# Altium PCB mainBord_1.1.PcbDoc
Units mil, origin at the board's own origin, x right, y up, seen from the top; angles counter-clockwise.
Board outline 3937.01 x 3149.61 mil, 2 copper layers (Top Layer, Bottom Layer); 51 components, 85 nets, 361 pads, 344 vias.
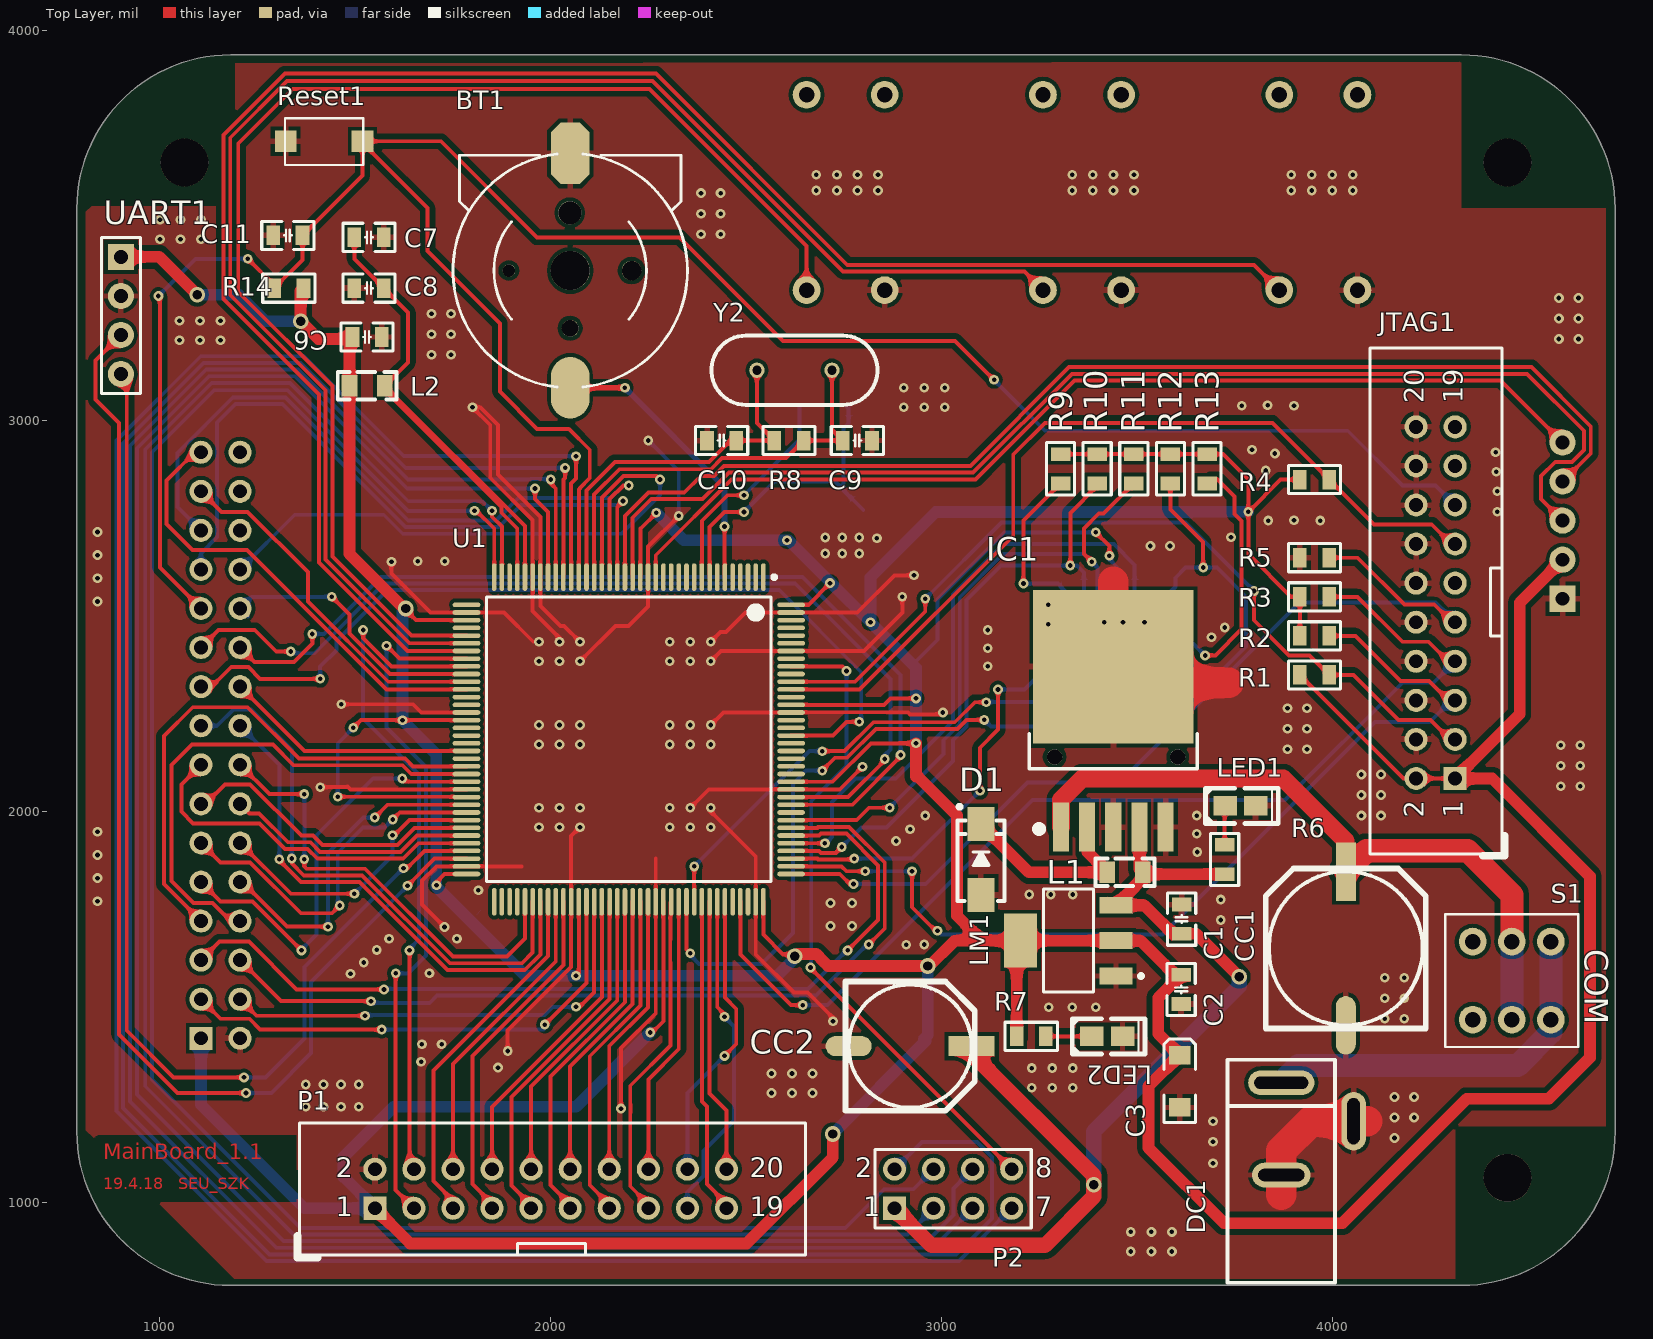
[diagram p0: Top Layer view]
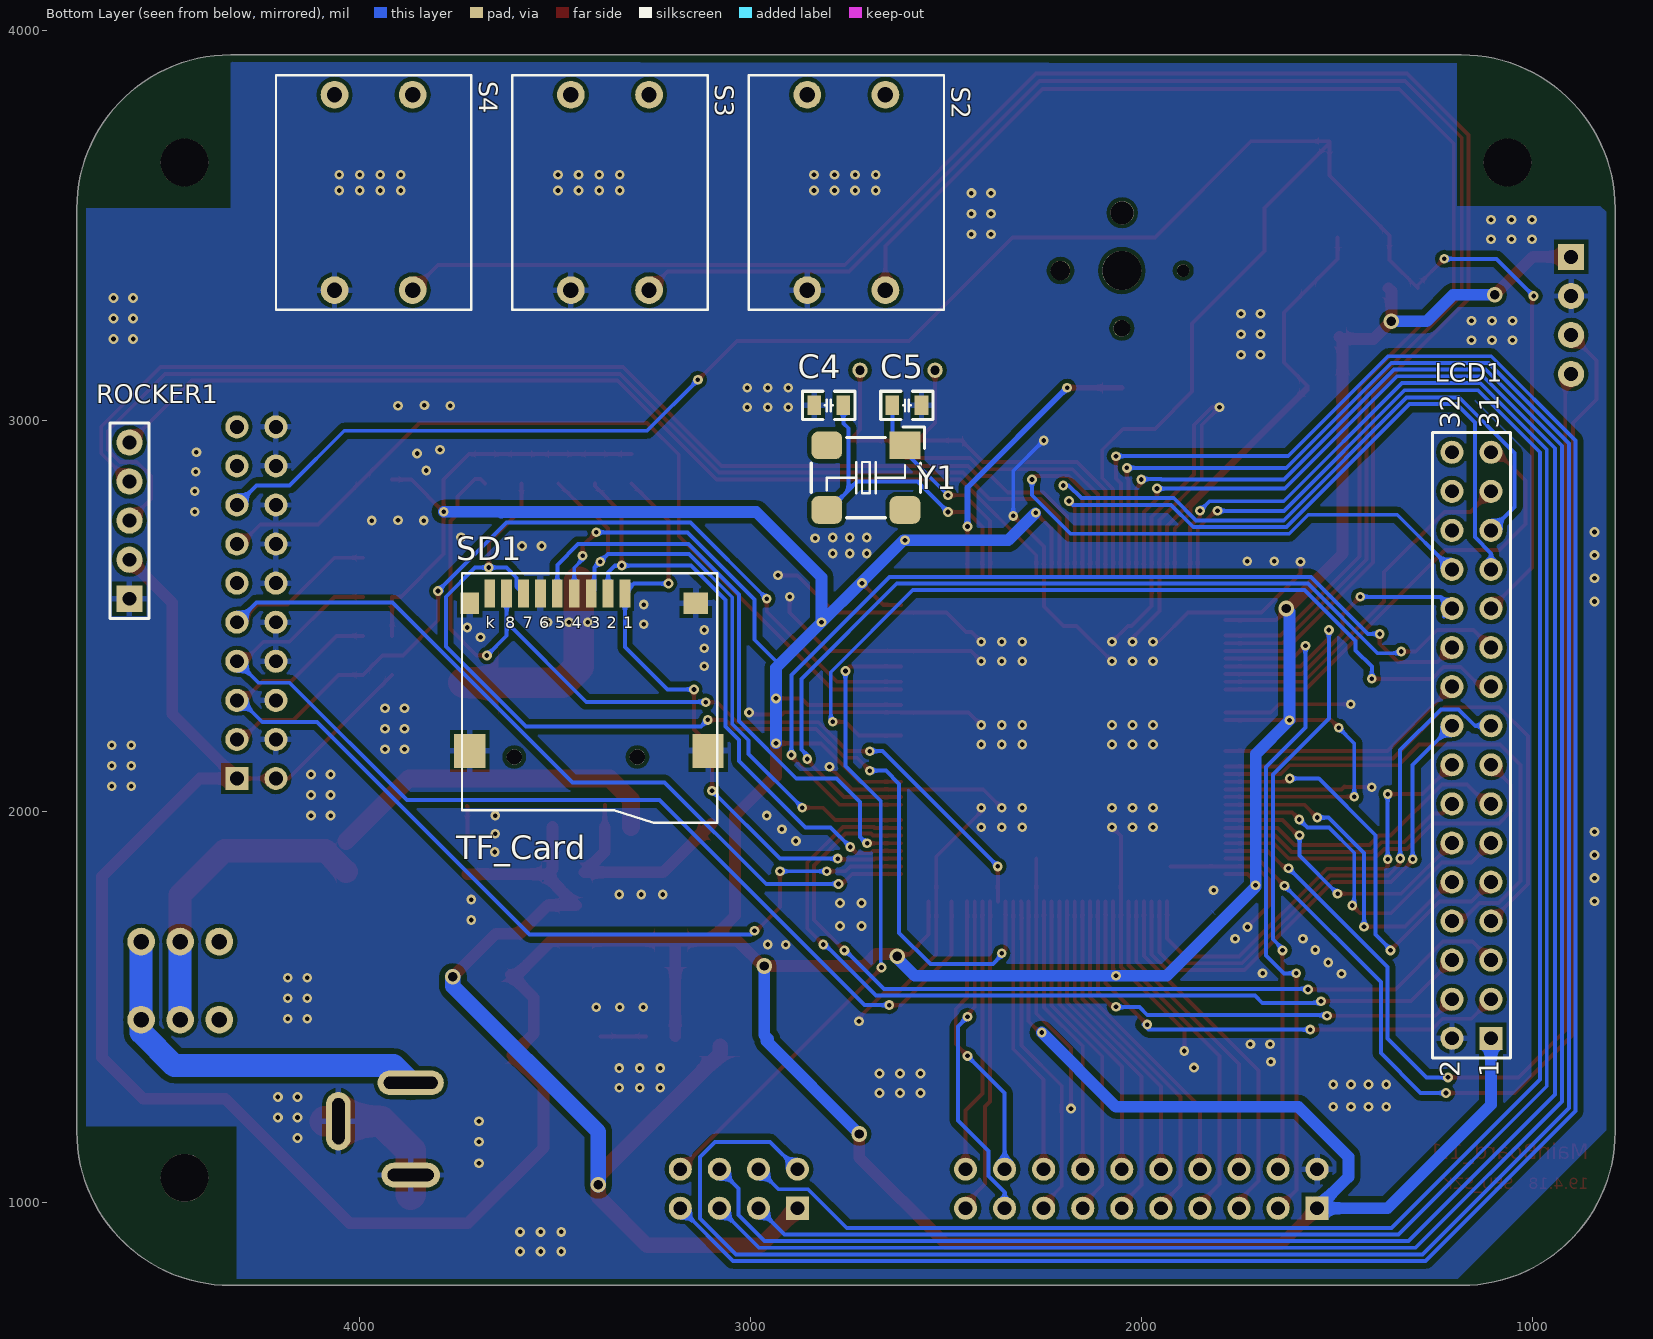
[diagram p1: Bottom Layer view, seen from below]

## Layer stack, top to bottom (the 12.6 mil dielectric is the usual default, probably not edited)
Top Solder: solder mask 0.4, Solder Resist, Dk 3.5
Top Layer: signal copper 1.4
Dielectric 1: dielectric 12.6, FR-4, Dk 4.8
Bottom Layer: signal copper 1.4
Bottom Solder: solder mask 0.4, Solder Resist, Dk 3.5

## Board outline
787.4,1181.1 787.4,3543.31 cw(c1181.1,3543.31) 1181.1,3937.01 4330.71,3937.01 cw(c4330.71,3543.31) 4724.41,3543.31 4724.41,1181.1 cw(c4330.71,1181.1) 4330.71,787.4 1181.1,787.4 cw(c1181.1,1181.1)

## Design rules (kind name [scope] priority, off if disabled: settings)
Clearance [InNamedPolygon('GND_L02_P017')] p1: gap=10 ignorepadtopadclearanceinfootprint=FALSE except(0: Arc-Hole Track-Hole SMDPad-Hole THPad-Hole Via-Hole Fill-Hole Poly-Hole Region-Hole Text-Hole; 15: Arc-Fill Arc-Poly Arc-Region Track-Fill Track-Poly Track-Region)
Clearance putuo [InNamedPolygon('Bottom Layer-No Net')] p2: gap=10 ignorepadtopadclearanceinfootprint=FALSE except(0: Arc-Hole Track-Hole SMDPad-Hole THPad-Hole Via-Hole Fill-Hole Poly-Hole Region-Hole Text-Hole; 15: Arc-Fill Arc-Poly Arc-Region Track-Fill Track-Poly Track-Region)
Clearance Clearance_1 [All] p3: gap=7 ignorepadtopadclearanceinfootprint=FALSE except(0: Via-Hole Fill-Hole Poly-Hole Region-Hole Text-Hole)
MinimumSolderMaskSliver [All] p1: minsoldermaskwidth=7
PolygonConnect [All] p1: thpad.connectstyle=Relief thpad.reliefconductorwidth=15 thpad.reliefentries=4 thpad.polygonreliefangle="90 Angle" thpad.airgapwidth=10 smdpad.connectstyle=Relief smdpad.reliefconductorwidth=15 smdpad.reliefentries=4 smdpad.polygonreliefangle="90 Angle" smdpad.airgapwidth=10 via.connectstyle=Direct via.reliefconductorwidth=10 via.reliefentries=4 via.polygonreliefangle="90 Angle" via.airgapwidth=10
RoomDefinition mainBord [InComponentClass('mainBord')] p1: confinementstyle=ConfineIn formatcopy=TRUE lockcomponents=FALSE outline 1181.1,3937.01 787.4,3543.31 787.4,1181.1 1181.1,787.4 4330.71,787.4 4724.41,1181.1 4724.41,3543.31 4330.71,3937.01
RoutingVias [All] p1: holewidth=12 width=25 viastyle="Through Hole" minholewidth=8 minwidth=20 maxholewidth=24 maxwidth=40
SilkToSilkClearance [All] p1 off: silktosilkclearance=10
SilkToSolderMaskClearance [IsPad] p1 off: minsilkscreentomaskgap=10 clearancetoexposedcopper=TRUE
SolderMaskExpansion [All] p1: expansion=4
Width 12V [InNetClass('12V')] p1: maxlimit=78.74 minlimit=39.37 preferedwidth=59.06 minimp=50.000000 maximp=50.000000 favimp=50.000000
Width 5V [InNet('5V')] p2: maxlimit=39.37 minlimit=30 preferedwidth=39.37 minimp=50.000000 maximp=50.000000 favimp=50.000000
Width 3.3V [InNet('3.3V')] p3: maxlimit=39.37 minlimit=10 preferedwidth=30 minimp=50.000000 maximp=50.000000 favimp=50.000000
Width [All] p4: maxlimit=78.74 minlimit=10 preferedwidth=10 minimp=50.000000 maximp=50.000000 favimp=50.000000
27 further rules are at their usual default settings.

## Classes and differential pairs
polygon class PolygonClass_1: GND_L02_P007

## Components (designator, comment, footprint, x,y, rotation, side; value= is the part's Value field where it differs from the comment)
BT1 "CR220" battery 2049.65,3486.41 r0 top
C1 "100nf" "C 0805_L" 3615,1725 r90 top value=100nF
C2 "100nf" "C 0805_L" 3613.89,1545 r270 top value=100nF
C3 "10uf" "CD A(3216)" 3610,1310 r270 top value=10uF
C4 "22pf" "C 0805_L" 2800,3040 r180 bottom value=22pF
C5 "22pf" "C 0805_L" 2600,3040 r0 bottom value=22pF
C6 "100nf" "C 0805_L" 1530,3215 r0 top value=100pF
C7 "100nf" "C 0805_L" 1535,3470 r0 top value=100nF
C8 "100nf" "C 0805_L" 1535,3340 r180 top value=100nF
C9 "22pf" "C 0805_L" 2785,2950 r180 top value=22pF
C10 "22pf" "C 0805_L" 2437.6,2950 r0 top value=22pF
C11 "100nf" "C 0805_L" 1327.6,3475 r0 top value=100nF
CC1 "680uf" "CM F(10*10.2)" 4035,1650 r90 top
CC2 "220uf" "CM E(8*10.2)" 2920,1400 r0 top
D1 "SS14" SMA 3101.56,1877.75 r90 top
DC1 "DC005" DC005座 3870,1070 r90 top
IC1 "LM2596-5.0V" TO263-5A 3440,1960.75 r0 top
JTAG1 "JTAG" JTAG20 4315,2085 r90 top
L1 "Inductor" "L 0805" 3470,1845 r0 top value=33uH
L2 "Inductor" "L 0805" 1530,3090 r0 top value=4.7uH
LCD1 "TFTLCD" HDR2X16 1105,1420 r90 bottom
LED1 "LED2" LED-0805 3726.26,2015 r0 top
LED2 "LED2" LED-0805 3385,1425 r0 top
LM1 "LM1117DT-3.3" SOT-223 3325,1670 r90 top
P1 "OUT1" JTAG20 1550,985 r0 top
P2 "OUT2" HDR2X4 2880,985 r0 top
R1 "10K" "R 0805_L" 3955,2350 r180 top
R2 "10K" "R 0805_L" 3955,2450 r180 top
R3 "10K" "R 0805_L" 3955,2550 r180 top
R4 "10K" "R 0805_L" 3955,2850 r180 top
R5 "10K" "R 0805_L" 3955,2650 r0 top
R6 "1K" "R 0805_L" 3725,1877.6 r270 top
R7 "1K" "R 0805_L" 3230,1425 r180 top
R8 "1M" "R 0805_L" 2610,2950 r0 top
R9 "5K" "R 0805_L" 3305,2877.6 r270 top
R10 "5K" "R 0805_L" 3398.75,2877.6 r270 top
R11 "5K" "R 0805_L" 3492.5,2877.6 r270 top
R12 "5K" "R 0805_L" 3586.25,2877.6 r270 top
R13 "5K" "R 0805_L" 3680,2877.6 r270 top
R14 "1K" "R 0805_L" 1330,3340 r0 top
Reset1 "SW-PB" 微动开关-1 1420,3715 r180 top
ROCKER1 "RK" HDR2.54-M-LI-5P 4590,2745 r90 bottom
S1 "SW-DPDT" 按键开关-1 4560,1667.6 r180 top
S2 "SW-PB" 微动开关-大-1-绿 2855,3335 r180 bottom
S3 "SW-PB" 微动开关-大-1-绿 3460,3335 r180 bottom
S4 "SW-PB" 微动开关-大-1-绿 4065,3335 r180 bottom
SD1 "TF_Card" "Micro SD" 3447.48,2140 r180 bottom
U1 "STM32F103ZET6" STM-LQFP144_N 2200,2185 r270 top
UART1 "Header 4" HDR2.54-LI-4P 900,3270 r270 top
Y1 "32.768K" "OSC 7050-4P" 2704.99,2855 r0 bottom
Y2 "XTAL" HC-49S 2623.94,3130 r0 top

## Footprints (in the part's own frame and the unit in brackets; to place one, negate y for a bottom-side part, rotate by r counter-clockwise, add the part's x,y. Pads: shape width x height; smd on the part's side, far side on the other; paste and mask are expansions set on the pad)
battery [mm]
  round 0.813 hole 0.813: 0(-3.979,-2.576)
  round 1.5 hole 1.5: 0(-0.016,1.174)
  round 1.1 hole 1.1: 0(0.009,-6.326)
  round 2.54 hole 2.54: 0(0.009,-2.576)
  round 1.27 hole 1.27: 0(3.997,-2.576)
  oct 2.5x4 smd: GBAT(0.009,5.044)
  oval 2.5x4 smd: VBAT(0.009,-10.196)
  silkscreen extent -7.61,-10.15 7.63,5
"C 0805_L" [mil] "无极性贴片电容"
  rect 35x50 smd: 1(-37.4,0) 2(37.4,0)
  silkscreen extent -67,-36 67,36, body extent -39,-24 39,24, height 20
"CD A(3216)" [mm] "长3.2mm，宽1.6mm，厚1.6mm"
  rect 1.2x1.4 smd: 1(-1.7,0) 2(1.7,0)
  silkscreen extent -2.74,-1.02 2.67,1.02, body extent -1.6,-0.8 1.6,0.8, height 1.6
"CM E(8*10.2)" [mm] "贴片电解电容，直径8mm，高10.2mm"
  rect 3x1.3 smd: 1(4,0)
  oval 3x1.3 smd: 2(-4,0)
  silkscreen extent -4.2,-4.2 4.2,4.2, body extent -4.5,-4.15 4.5,4.15, height 10.2
"CM F(10*10.2)" [mm] "贴片电解电容，直径10mm，高10.2mm"
  rect 3.8x1.3 smd: 1(5,0)
  oval 3.8x1.3 smd: 2(-5,0)
  silkscreen extent -5.2,-5.2 5.2,5.2, body extent -5.8,-5.15 5.8,5.15, height 10.2
DC005座 [mm]
  oval 3.8x1.6 hole 0.8 slot 3 at 0 deg: CON(3.5,-4.7)
  oval 1.6x3.8 hole 0.8 slot 3 at 90 deg: GND(0,0)
  oval 1.6x4.3 hole 0.8 slot 3.5 at 90 deg: VCC(6,0)
  silkscreen extent -7,-3.5 7.49,3.5
HC-49S [mm]
  round 1 hole 0.6: XTAL_1(-2.44,0) XTAL_2(2.44,0)
  silkscreen extent -5.4,-2.25 5.4,2.25
HDR2.54-LI-4P [mm] "排针，4脚"
  rect 1.7x1.7 hole 0.9: 1(-3.81,0)
  round 1.7 hole 0.9: 2(-1.27,0) 3(1.27,0) 4(3.81,0)
  silkscreen extent -5.08,-1.27 5.08,1.27, body extent -5.08,-1.27 5.08,1.27, height 8.5
HDR2.54-M-LI-5P [mm] "排母，5脚"
  rect 1.7x1.7 hole 0.9: 1(-5.08,0)
  round 1.7 hole 0.9: 2(-2.54,0) 3(0,0) 4(2.54,0) 5(5.08,0)
  silkscreen extent -6.35,-1.27 6.35,1.27, body extent -6.35,-1.27 6.35,1.27, height 8.5
HDR2X4 [mm] "Connector; Header; 4x2 Position"
  rect 1.5x1.5 hole 0.9: 1(0,0)
  round 1.5 hole 0.9: 2(0,2.54) 3(2.54,0) 4(2.54,2.54) 5(5.08,0) 6(5.08,2.54) 7(7.62,0) 8(7.62,2.54)
  silkscreen extent -1.27,-1.27 8.89,3.81
HDR2X16 [mm] "Connector; Header; 16x2 Position"
  rect 1.5x1.5 hole 0.9: 1(0,0)
  round 1.5 hole 0.9: 2(0,2.54) 3(2.54,0) 4(2.54,2.54) 5(5.08,0) 6(5.08,2.54) 7(7.62,0) 8(7.62,2.54) 9(10.16,0) 10(10.16,2.54) 11(12.7,0) 12(12.7,2.54) 13(15.24,0) 14(15.24,2.54) 15(17.78,0) 16(17.78,2.54) 17(20.32,0) 18(20.32,2.54) 19(22.86,0) 20(22.86,2.54) 21(25.4,0) 22(25.4,2.54) 23(27.94,0) 24(27.94,2.54) 25(30.48,0) 26(30.48,2.54) 27(33.02,0) 28(33.02,2.54) 29(35.56,0) 30(35.56,2.54) 31(38.1,0) 32(38.1,2.54)
  silkscreen extent -1.27,-1.27 39.37,3.81
JTAG20 [mm]
  rect 1.5x1.5 hole 0.9: 1(0,0)
  round 1.5 hole 0.9: 2(0,2.54) 3(2.54,0) 4(2.54,2.54) 5(5.08,0) 6(5.08,2.54) 7(7.62,0) 8(7.62,2.54) 9(10.16,0) 10(10.16,2.54) 11(12.7,0) 12(12.7,2.54) 13(15.24,0) 14(15.24,2.54) 15(17.78,0) 16(17.78,2.54) 17(20.32,0) 18(20.32,2.54) 19(22.86,0) 20(22.86,2.54)
  silkscreen extent -5.03,-3.23 27.99,5.54, body extent -5.01,-3.18 27.99,5.62, height 10.9
"L 0805" [mil] "小功率贴片电感"
  rect 40x55 smd: 1(-45,0) 2(45,0)
  silkscreen extent -75,-35 75,35, body extent -39,-24 39,24, height 35
LED-0805 [mil]
  rect 60x50 smd: 1(0,0) 2(78.74,0)
  silkscreen extent -50,-45 136,45
"Micro SD" [mm]
  round 1 hole 1 unplated: 0(-4,0) 0(4,0)
  rect 0.7x1.8 smd: 1(3.2,10.627) 2(2.1,10.627) 3(1,10.627) 4(-0.1,10.627) 5(-1.2,10.627) 6(-2.3,10.627) 7(-3.4,10.627) 8(-4.5,10.627) 9(-5.6,10.627)
  rect 2.032x2.2 smd: 10(-6.9,0.4) 10(8.6,0.4)
  rect 1.2x1.4 smd: 10(-6.9,10)
  rect 1.6x1.4 smd: 10(7.8,10)
  silkscreen extent -7.4,-4.28 9.2,11.94, body extent 0,0 0,0
"OSC 7050-4P" [mm] "7mm*5mm*1.3mm(长*宽*高)"
  rect 2x1.8 smd: 1(-2.54,-2.1)
  rrect50% 2x1.8 smd: 2(2.54,-2.1) 3(2.54,2.1) 4(-2.54,2.1)
  silkscreen extent -3.81,-3.3 3.56,2.61, body extent -3.5,-2.5 3.5,2.5, height 1.36
"R 0805_L" [mil] "1/8W贴片电阻"
  rect 35x50 smd: 1(-37.4,0) 2(37.4,0)
  silkscreen extent -67,-36 67,36, body extent -39,-25 39,25, height 20
SMA [mm] "4.5x2.6*2.2mm（长宽高，不包括引脚）"
  rect 2.2x1.75 smd: 1(-2.3,0) 2(2.3,0)
  silkscreen extent -2.7,-1.52 3.56,1.52, body extent -2.53,-1.3 2.58,1.3, height 2.15
SOT-223 [mm] "SOT-223/SC-73; 4 Leads; Body 6.7 x 7.3 mm, inc. leads (LxW max)"
  rect 1.1x2.15 smd: 1(-2.3,-3.1) 2(0,-3.1) 3(2.3,-3.1)
  rect 3.5x2.15 smd: 4(0,3.1)
  silkscreen extent -3.35,-4.85 3.35,1.63, body extent -3.25,-3.58 3.25,3.38, height 1.65
STM-LQFP144_N [mm] "Thin QFP, 144-Leads, Body 20x20mm, Pitch 0.5mm, IPC Medium Density"
  oval 1.8x0.3 smd: 1(-10.55,8.75) 2(-10.55,8.25) 3(-10.55,7.75) 4(-10.55,7.25) 5(-10.55,6.75) 6(-10.55,6.25) 7(-10.55,5.75) 8(-10.55,5.25) 9(-10.55,4.75) 10(-10.55,4.25) 11(-10.55,3.75) 12(-10.55,3.25) 13(-10.55,2.75) 14(-10.55,2.25) 15(-10.55,1.75) 16(-10.55,1.25) 17(-10.55,0.75) 18(-10.55,0.25) 19(-10.55,-0.25) 20(-10.55,-0.75) 21(-10.55,-1.25) 22(-10.55,-1.75) 23(-10.55,-2.25) 24(-10.55,-2.75) 25(-10.55,-3.25) 26(-10.55,-3.75) 27(-10.55,-4.25) 28(-10.55,-4.75) 29(-10.55,-5.25) 30(-10.55,-5.75) 31(-10.55,-6.25) 32(-10.55,-6.75) 33(-10.55,-7.25) 34(-10.55,-7.75) 35(-10.55,-8.25) 36(-10.55,-8.75) 73(10.55,-8.75) 74(10.55,-8.25) 75(10.55,-7.75) 76(10.55,-7.25) 77(10.55,-6.75) 78(10.55,-6.25) 79(10.55,-5.75) 80(10.55,-5.25) 81(10.55,-4.75) 82(10.55,-4.25) 83(10.55,-3.75) 84(10.55,-3.25) 85(10.55,-2.75) 86(10.55,-2.25) 87(10.55,-1.75) 88(10.55,-1.25) 89(10.55,-0.75) 90(10.55,-0.25) 91(10.55,0.25) 92(10.55,0.75) 93(10.55,1.25) 94(10.55,1.75) 95(10.55,2.25) 96(10.55,2.75) 97(10.55,3.25) 98(10.55,3.75) 99(10.55,4.25) 100(10.55,4.75) 101(10.55,5.25) 102(10.55,5.75) 103(10.55,6.25) 104(10.55,6.75) 105(10.55,7.25) 106(10.55,7.75) 107(10.55,8.25) 108(10.55,8.75)
  oval 0.3x1.8 smd: 37(-8.75,-10.55) 38(-8.25,-10.55) 39(-7.75,-10.55) 40(-7.25,-10.55) 41(-6.75,-10.55) 42(-6.25,-10.55) 43(-5.75,-10.55) 44(-5.25,-10.55) 45(-4.75,-10.55) 46(-4.25,-10.55) 47(-3.75,-10.55) 48(-3.25,-10.55) 49(-2.75,-10.55) 50(-2.25,-10.55) 51(-1.75,-10.55) 52(-1.25,-10.55) 53(-0.75,-10.55) 54(-0.25,-10.55) 55(0.25,-10.55) 56(0.75,-10.55) 57(1.25,-10.55) 58(1.75,-10.55) 59(2.25,-10.55) 60(2.75,-10.55) 61(3.25,-10.55) 62(3.75,-10.55) 63(4.25,-10.55) 64(4.75,-10.55) 65(5.25,-10.55) 66(5.75,-10.55) 67(6.25,-10.55) 68(6.75,-10.55) 69(7.25,-10.55) 70(7.75,-10.55) 71(8.25,-10.55) 72(8.75,-10.55) 109(8.75,10.55) 110(8.25,10.55) 111(7.75,10.55) 112(7.25,10.55) 113(6.75,10.55) 114(6.25,10.55) 115(5.75,10.55) 116(5.25,10.55) 117(4.75,10.55) 118(4.25,10.55) 119(3.75,10.55) 120(3.25,10.55) 121(2.75,10.55) 122(2.25,10.55) 123(1.75,10.55) 124(1.25,10.55) 125(0.75,10.55) 126(0.25,10.55) 127(-0.25,10.55) 128(-0.75,10.55) 129(-1.25,10.55) 130(-1.75,10.55) 131(-2.25,10.55) 132(-2.75,10.55) 133(-3.25,10.55) 134(-3.75,10.55) 135(-4.25,10.55) 136(-4.75,10.55) 137(-5.25,10.55) 138(-5.75,10.55) 139(-6.25,10.55) 140(-6.75,10.55) 141(-7.25,10.55) 142(-7.75,10.55) 143(-8.25,10.55) 144(-8.75,10.55)
  silkscreen extent -10.67,-9.25 9.25,9.58, body extent -10,-10 10,10, height 1.6
TO263-5A [mm] "263，5脚晶体管"
  rect 1.05x3.2 smd: 1(-3.4,0) 2(-1.7,0) 3(0,0) 4(1.7,0) 5(3.4,0)
  rect 10.45x10 smd: 3(0,10.414)
  silkscreen extent -5.46,-0.33 5.46,6.04, body extent -5,-0.01 5,13.32, height 4.5
微动开关-1 [mm]
  rect 1.4x1.4 smd: 1(-2.5,-0.024) 2(2.5,-0.024)
  silkscreen extent -2.54,-1.52 2.54,1.52, body extent -2.5,-1.52 2.5,1.48, height 2.1
微动开关-大-1-绿 [mm]
  round 1.8 hole 1: 1(0,0) 2(0,12.7) 3(5.08,0) 4(5.08,12.7)
  silkscreen extent -3.81,-1.27 8.89,13.97, body extent -3.46,-0.51 8.54,13.37, height 10
按键开关-1 [mm]
  round 1.8 hole 1: 1(0,0) 2(2.54,0) 3(5.08,0) 4(0,5.08) 5(2.54,5.08) 6(5.08,5.08)
  silkscreen extent -1.78,-1.78 6.86,6.86, body extent -1.71,-1.78 6.79,6.72, height 14.5

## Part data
BT1: library part Battery, "Multicell Battery"
C1 C2 C4 C5 C6 C7 C8 C9 C10 C11: library part Cap, "Capacitor"
C3: library part "Cap Pol2", "Polarized Capacitor (Axial)"
CC1 CC2: library part CAP-T, "贴片铝解电容"
D1: "肖特基二极管"
IC1: library part LM2596-5.0, "DC降压芯片"
JTAG1 P1: library part "Header 10X2", "Header, 10-Pin, Dual row"
L1: Manufacturer="Generic Components"
LCD1: library part MHDR2X16, "Header, 16-Pin, Dual row"
LED1 LED2: "Typical RED, GREEN, YELLOW, AMBER GaAs LED"
LM1: "800mA Low-Dropout Linear Regulator, 3-pin TO-252", Manufacturer="National Semiconductor", PackageTopMarking=NSUZXYTT*LM1117*DT-3.3, PowerWise=N
P2: library part "Header 4X2", "Header, 4-Pin, Dual row"
R1 R2 R3 R4 R5 R6 R7 R8 R9 R10 R11 R12 R13 R14: library part Res2, "Resistor"
Reset1: "Switch"
ROCKER1: library part MHDR1X5, "Header, 5-Pin"
S2 S3 S4: library part 微动开关
SD1: "TF卡座"
U1: "ARM Cortex-M3 32-bit MCU, 512 KB Flash, 64 KB Internal RAM, 112 I/Os, 144-pin LQFP, -40 to 85 degC, Tray", I/Os (High Current)=112, Operating Frequency(F) (Processor speed) (MHz)=72, Supplier Part Number 1=497-6442-ND, Supply Voltage(Vcc) min (V)=2
UART1: "Header, 4-Pin"
Y1: library part XTAL, "Crystal Oscillator"
Y2: "Crystal Oscillator"

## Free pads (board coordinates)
  round 122.05 hole 122.05 unplated: 2(1062.99,3661.42) 3(4448.82,3661.42) 4(4448.82,1062.99)

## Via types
v1: diameter 25, hole 12, Top Layer to Bottom Layer, 336 vias
v2: diameter 40, hole 24, Top Layer to Bottom Layer, 8 vias

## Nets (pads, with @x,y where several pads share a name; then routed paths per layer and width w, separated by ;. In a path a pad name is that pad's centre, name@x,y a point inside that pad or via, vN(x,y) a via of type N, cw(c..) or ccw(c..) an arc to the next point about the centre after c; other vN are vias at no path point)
3.3V: C2.1 C3.1 C6.1 JTAG1.1 JTAG1.2 L2.1 LCD1.1 LM1.2 LM1.4 P1.1 R1.2 R2.2 R3.2 R4.2 R7.2 R9.1 R10.1 R11.1 R12.1 R13.1 R14.2 ROCKER1.2 SD1.4 U1.17 U1.39 U1.52 U1.62 U1.72 U1.84 U1.95 U1.108 U1.121 U1.131 U1.144 UART1.1 | length 19886.3
  Top Layer w10: R14.2 R14.2@1367.6,3340 ; v1(1455,2038.18) 1783.83,2038.18 U1.62 ; v1(1495,2215) 1514.21,2234.21 v1(1620.79,2234.21) U1.52 ; v2@1628.54,2516.58 1655,2490.12 U1.39 ; v1(1708,1812) 1708,1820 1728.51,1840.51 U1.72 ; v1(2065,1580) 2070,1580 2070,1587.65 2072.05,1589.7 U1.84 ; U1.17 2229.53,2725 2230.5,2725 v1(2270.5,2765) ; v1(2255,1435) 2260,1435 2288.58,1463.58 U1.95 ; U1.108 2544.49,1685.51 2595,1635 2630,1635 v2(2625,1630) ; U1.121 2721.73,2076.73 2820,2175 v1(2935,2175) ; U1.131 2853,2273.58 2869.42,2290 v1(2935,2290) ; U1.144 2659.49,2529.49 v1(2715,2585) ; R9.1 R10.1 R11.1 R12.1 R13.1 3720.69,2915 3785.58,2850.11 v1@3785.58,2775.55 ; v1(3395,2715) 3430,2680 v1(3430,2655) ; R1.2 4182.61,2085 JTAG1.2 JTAG1.1 ; R2.2 R3.2 3895,2550 3785.58,2659.42 v1(3785.58,2767.51) 3868.08,2850 R4.2
  Top Layer w30: UART1.1 997.84,3420 v2(1095,3322.84) ; R14.2 1360,3332.6 v2(1360,3255) 1405,3210 C6.1@1487.6,3210 ; C6.1 C6.1@1487.6,3210 ; P1.1 1640,895 2501.91,895 2721.73,1114.83 v2(2721.73,1175) ; v2@1627.08,2518.04 1485,2660.12 L2.1 1485,3207.4 C6.1@1487.6,3210 ; v2@2630,1635 2630.87,1635.87 2679.29,1635.87 2699.5,1615.66 2699.5,1615.5 2710,1605 v2(2965,1605) 2965,1601.28 3033.72,1670 3103.84,1670 ; v1(2935,2175) 2935,2090 2940,2090 3040,1990 3040,1733.84 3103.84,1670 ; R7.2 3192.6,1659.65 LM1.4 ; ROCKER1.2 4480,2535 4480,2250 JTAG1.1 4410,2085 4660,1835 4660,1370 4555,1265 4345,1265 4026.49,946.49 3723.51,946.49 3530,1140 3530,1296.93 C3.1 3555,1431.93 3555,1523.51 C2.1 3597.6,1582.4 3510,1670 LM1.2 LM1.4 ; 3103.84,1670 LM1.4
  Bottom Layer w10: v1(1455,2038.18) 1455,2175 v1(1495,2215) ; 2930,2373.66 2930,2380 2990,2440 2990,2543.15 3161.85,2715 v1(3395,2715) ; v1(3430,2655) 3430,2645.68 3451.42,2624.26 SD1.4
  Bottom Layer w30: v2(1095,3322.84) 1202.16,3322.84 1270,3255 v2(1360,3255) ; LCD1.1 1105,1250 1370,985 P1.1 1470,1065 1470,1117.14 1597.86,1245 2065,1245 v1(2255,1435) ; v2(1629.04,2520) 1620.79,2511.75 v1(1620.79,2234.21) 1707.44,2147.56 v1@1707.44,1812 ; v1@1707.44,1807.56 1935,1580 v1(2065,1580) 2580,1580 2630,1630 v2(2625,1630) ; v1@2271.84,2763.66 2340.5,2695 v1(2605,2695) 2608.66,2695 2715,2588.66 v1(2715,2585) 2718.66,2585 v1(2818.66,2485) ; v2(2721.73,1175) 2960,1413.27 2955,1418.27 2965,1428.27 v2(2965,1605) ; v1(2935,2175) v1(2935,2290) 2935,2368.66 2930,2373.66 v1(2818.66,2485) ; v1(3785.58,2767.51) 3640.69,2767.51 3638.18,2765 3636.18,2767 2985.66,2767 2818.66,2600 v1(2818.66,2485)
5V: C1.1 CC2.1 IC1.4 L1.2 LM1.3 P2.1 R6.2 | length 2636.6
  Top Layer w30: IC1.4 3506.93,1853.07 L1.2 ; R6.2 3519.8,1840.2 L1.2 ; v2(3762.01,1577.5) 3651.91,1687.6 C1.1 3592.4,1687.6 3519.45,1760.55 LM1.3 3515,1828.5 L1.2
  Top Layer w39.37: P2.1 2975,890 3265,890 3390,1015 v2(3390,1045) 3390,1068.66 3077.48,1381.18 CC2.1
  Bottom Layer w39.37: v2(3390,1045) 3390,1180.99 3762.01,1552.99 v2(3762.01,1577.5)
12V: CC1.1 IC1.1 S1.2 S1.5 | length 1700.9
  Top Layer w45: IC1.1 3306.14,2030.97 3360.17,2085 3875,2085 4035,1925
  Top Layer w59.06: CC1.1 4088.15,1900 4346.87,1900 4460,1786.87 S1.2
  Bottom Layer w59.06: S1.5 S1.2
BL_EN: LCD1.24 U1.46 | length 731
  Top Layer w10: v1(1440,2550) 1485,2505 1485,2455.94 1588.62,2352.32 U1.46
  Bottom Layer w10: LCD1.24@1225,2500 LCD1.24 1235,2550 v1(1440,2550)
DRIVER_OUT1: P1.13 U1.92 | length 859
  Top Layer w10: P1.13 2150,995 2100,1045 2100,1374.04 2229.53,1503.57 U1.92
DRIVER_OUT2: P1.14 U1.93 | length 725.7
  Top Layer w10: P1.14 2150,1400 2249.21,1499.21 U1.93
DRIVER_OUT3: P1.15 U1.96 | length 848.2
  Top Layer w10: P1.15 2250,995 2203.64,1041.36 2203.64,1228.99 2204.5,1229.85 2204.5,1250.15 2203.64,1251.01 2203.64,1298.64 2306.49,1401.49 2306.49,1614.24 2306.14,1614.59 2306.14,1672.19 2306.49,1672.54 2306.49,1767.87 U1.96
DRIVER_OUT4: P1.16 U1.97 | length 716.9
  Top Layer w10: P1.16 2250,1315 2327.95,1392.95 U1.97
DRIVER_OUT5: P1.17 U1.102 | length 860.6
  Top Layer w10: U1.102 2426.38,1499.69 2451.06,1475 v1(2445,1475)
  Bottom Layer w10: P1.17 2350,1026.27 2391.53,1067.8 2391.53,1131.53 2469.5,1209.5 2469.5,1450.5 v1(2445,1475)
DRIVER_OUT6: P1.18 U1.103 | length 748.4
  Top Layer w10: v1(2445,1375) 2475,1405 2475,1495 2446.06,1523.94 U1.103
  Bottom Layer w10: P1.18 2350,1280 v1(2445,1375)
DRIVER_PWM1: P1.19 U1.100 | length 810.7
  Top Layer w10: U1.100 2387.01,1258.19 2400,1245.2 2400,1046.69 2450,996.69 P1.19
DRIVER_PWM2: P1.20 U1.101 | length 702.6
  Top Layer w10: U1.101 2406.69,1278.31 2450,1235 P1.20
FSMC_A10: LCD1.20 U1.56 | length 647.8
  Top Layer w10: LCD1.20 1369.53,2155.47 U1.56
FSMC_D0: LCD1.3 U1.85 | length 1296.3
  Top Layer w10: LCD1.3 1155,1470 1228.73,1470 1256.48,1442.25 v1(1567.4,1442.25) ; v1(1985,1455) 1985,1455.32 2091.73,1562.05 U1.85
  Bottom Layer w10: v1(1567.4,1442.25) 1982.25,1442.25 1995,1455 v1(1985,1455)
FSMC_D1: LCD1.4 U1.86 | length 1181.4
  Top Layer w10: LCD1.4 1247.26,1477.74 v1(1525,1477.74) ; v1(2065,1500.67) 2073.33,1500.67 2074,1500 2111.42,1537.42 U1.86
  Bottom Layer w10: v1(1525,1477.74) 1526.76,1479.5 1984.85,1479.5 2005.1,1499.75 2064.08,1499.75 v1(2065,1500.67)
FSMC_D2: LCD1.5 U1.114 | length 2275.2
  Top Layer w10: LCD1.5 1152.6,1667.6 1227.4,1667.6 1350,1545 v1(1573.5,1545) ; U1.114 2686.89,1938.94 2691.71,1943.75 2757.01,1943.75 2838,1862.76 2838,1723 v1(2760,1645)
  Bottom Layer w10: v1(1573.5,1545) 1575,1546.5 2658.85,1546.5 2757.35,1645 v1(2760,1645)
FSMC_D3: LCD1.6 U1.115 | length 2221.3
  Top Layer w10: LCD1.6 1310,1515 v1(1540,1515) ; U1.115 2682.53,1958.62 2684.66,1960.75 2764.05,1960.75 2855,1869.8 2855,1700.96 v1(2814.04,1660)
  Bottom Layer w10: v1(1540,1515) 1544.5,1510.5 1690.5,1510.5 1709.5,1529.5 2679.15,1529.5 2809.65,1660 v1(2814.04,1660)
FSMC_D4: LCD1.7 U1.58 | length 1380.7
  Top Layer w10: LCD1.7 1010,1815 1010,2193.42 1083.95,2267.38 1223.83,2267.38 1355.41,2135.79 1627.9,2135.79 1647.59,2116.1 U1.58
FSMC_D5: LCD1.8 U1.59 | length 1322.3
  Top Layer w10: LCD1.8 1180.96,1720 1134.33,1766.63 1086.14,1766.63 1030,1822.77 1030,2120 1082.01,2172.01 1288.95,2172.01 1342.17,2118.79 1620.86,2118.79 1643.23,2096.42 U1.59
FSMC_D6: LCD1.9 U1.60 | length 1088
  Top Layer w10: LCD1.9 1155,1770 1237.26,1770 v1(1362.26,1645) ; v1(1620,2085) 1628.27,2076.73 U1.60
  Bottom Layer w10: v1(1362.26,1645) 1362.26,1647.26 1400.4,1685.4 1400.4,1939.6 1545.81,2085 v1(1620,2085)
FSMC_D7: LCD1.10 U1.63 | length 866.6
  Top Layer w10: LCD1.10 1211.31,1820 1325.66,1705.64 v1(1430,1705.64) ; v1(1550,1985) 1582.68,2017.68 U1.63
  Bottom Layer w10: v1(1430,1705.64) 1430,1894.04 1520.96,1985 v1(1550,1985)
FSMC_D8: LCD1.11 U1.64 | length 947.2
  Top Layer w10: LCD1.11 1155,1870 1230.92,1870 1360.92,1740 1440,1740 v1(1460,1760) ; v1(1595.74,1980) 1613.73,1997.99 U1.64
  Bottom Layer w10: v1(1460,1760) 1455,1765 1455,1895 1519.5,1959.5 1575.24,1959.5 v1(1595.74,1980)
FSMC_D9: LCD1.12 U1.65 | length 742.3
  Top Layer w10: LCD1.12 1335,1790 v1(1497.6,1790) ; v1(1595,1940) 1600.7,1940 1639.01,1978.31 U1.65
  Bottom Layer w10: v1(1497.6,1790) 1595,1887.4 v1(1595,1940)
FSMC_D10: LCD1.13 U1.66 | length 782.6
  Top Layer w10: LCD1.13 1116.03,2020 1166.03,2070 1230.96,2070 1362.26,1938.7 1392.04,1938.7 1415.73,1915 1608.06,1915 1651.69,1958.62 U1.66
FSMC_D11: LCD1.14 U1.67 | length 648
  Top Layer w10: LCD1.14 1229.53,1995.47 1253.57,1995.47 1327.35,1921.7 1385,1921.7 1409.69,1897 1615.64,1897 1657.57,1938.94 U1.67
FSMC_D12: LCD1.15 U1.68 | length 936.3
  Top Layer w10: LCD1.15 1055,2070 1055,2000 1085,1970 1255,1970 1320.3,1904.7 1377.95,1904.7 1402.65,1880 1622.68,1880 1661.93,1919.25 U1.68
FSMC_D13: LCD1.16 U1.77 | length 1155
  Top Layer w10: LCD1.16 1280,2045 v1(1369.53,2045) ; v1(1369.53,1878.47) 1369.53,1859.47 1375,1854 1465.74,1854 ; 1465.77,1854.03 1524.57,1854.03 1749.6,1629 1888.25,1629 1934.25,1675 U1.77
  Bottom Layer w10: v1(1369.53,1878.47) v1(1369.53,2045)
FSMC_D14: LCD1.17 U1.78 | length 1446.7
  Top Layer w10: v1(1337.53,1880.2) 1337.53,1867.43 1367.96,1837 1472.78,1837 ; 1472.81,1837.03 1517.53,1837.03 1742.55,1612 1926.58,1612 1953.94,1639.36 U1.78
  Bottom Layer w10: LCD1.17 1146.27,2220 1187.8,2261.53 1233.47,2261.53 1337.53,2157.47 v1(1337.53,1880.2)
FSMC_D15: LCD1.18 U1.79 | length 1321.7
  Top Layer w10: v1(1305.53,1878.47) 1305.53,1875.39 1360.92,1820 1479.82,1820 ; 1479.85,1820.03 1510.48,1820.03 1735.51,1595 1933.62,1595 1973.62,1635 U1.79
  Bottom Layer w10: LCD1.18 1305.53,2119.47 v1(1305.53,1878.47)
FSMC_NE4: LCD1.19 U1.127 | length 2254.6
  Top Layer w10: LCD1.19 1132.49,2320 1182.49,2370 1226.22,2370 1256.22,2340 v1(1410,2340) ; U1.127 2722.44,2194.84 2757.6,2230 v1(2790,2230)
  Bottom Layer w10: v1(1410,2340) 1410,2371.31 1451.5,2412.81 1451.5,2436.5 1581.92,2566.92 2585.05,2566.92 2795,2356.97 2795,2235 v1(2790,2230)
FSMC_NOE: LCD1.22 U1.118 | length 2454.6
  Top Layer w10: LCD1.22 1241.98,2383.02 1342.67,2383.02 1390,2430.35 v1(1390,2455) ; U1.118 2772.33,2017.68 2895.65,2141 v1(2895.65,2145)
  Bottom Layer w10: v1(1390,2455) 1420,2455 1565.92,2600.92 2644.08,2600.92 2895.65,2349.35 v1(2895.65,2145)
FSMC_NWE: LCD1.21 U1.119 | length 2476.6
  Top Layer w10: LCD1.21 1150,2465 1242.64,2465 1297.64,2410 v1(1335,2410) ; U1.119 2760.94,2037.36 2855,2131.42 v1(2855,2135)
  Bottom Layer w10: v1(1335,2410) 1339.5,2405.5 1395.5,2405.5 1573.92,2583.92 2626.08,2583.92 2870,2340 2870,2158.93 2855,2143.93 v1(2855,2135)
GND: BT1.GBAT C1.2 C2.2 C3.2 C4.1 C5.1 C6.2 C7.2 C8.2 C9.1 C10.1 C11.1 CC1.2 CC2.2 D1.1 DC1.CON DC1.GND IC1.3 IC1.5 JTAG1.4 JTAG1.6 JTAG1.8 JTAG1.10 JTAG1.12 JTAG1.14 JTAG1.16 JTAG1.18 JTAG1.20 LCD1.2 LED1.2 LED2.2 LM1.1 P1.2 R5.1 Reset1.2 ROCKER1.1 S2.1 S3.1 S4.1 SD1.6 SD1.10 U1.16 U1.30 U1.31 U1.38 U1.51 U1.61 U1.71 U1.83 U1.94 U1.107 U1.120 U1.130 U1.138 U1.143 UART1.2 | length 8929.8
  Top Layer w10: v1(1410,2062.8) 1477.45,2062.8 1479.65,2065 1487.6,2057.05 U1.61 ; v1(1464.01,2275) 1647.57,2275 1668.67,2253.9 U1.51 ; v1(1592.41,2640) 1592.41,2610.16 1692.77,2509.8 U1.38 1880.63,2509.8 1955.43,2435 v1(1970,2435) ; v1(1728.51,1705) 1671.14,1762.38 1671.14,1823.86 1707.47,1860.2 U1.71 1925,1860.2 ; v1(1890,1387.64) 1890,1439.65 2052.36,1602.01 U1.83 2052.36,1937.36 v1(2075,1960) ; v1(2022.5,2435) 2022.5,2444.94 1953.94,2513.5 U1.31 1953.94,2746.06 1845.32,2854.68 1845.32,2990 v1@1800.32,3035 ; v1(2075,2385) 2165.43,2475.43 2199.64,2475.43 2249.21,2525 2249.21,2678.32 v1(2327.95,2757.06) ; v1(2075,2435) 2034.57,2475.43 2025,2475.43 1973.62,2526.81 U1.30 1973.62,2754.22 1865,2862.84 1865,2990 1820,3035 v1@1800.32,3035 ; v1(2180,1240) 2180,1395 2268.9,1483.9 U1.94 2268.9,1880.2 ; v1(2357.5,2010) 2404.55,2057.05 U1.120 2740,2057.05 v1(2797.95,2115) ; v1(2410,2010) 2410,1999.75 2524.8,1884.95 U1.107 2524.8,1635 2622.87,1536.93 2658.07,1536.93 2722.44,1472.56 v1(2722.44,1463.58) ; v1(2410,2222.01) 2441.89,2253.9 U1.130 ; v1(2410,2385) 2436.38,2411.38 U1.138 2801.52,2411.38 2801.52,2411.52 2900,2510 v1(2900,2550) ; v1(2410,2435) 2435,2460 2448.91,2460 2498.71,2509.8 U1.143 2784.8,2509.8 2880,2605 v1(2930,2605) ; v1(3003.9,2253.9) 2999.08,2249.08 2919.63,2249.08 2914.21,2254.5 U1.130@2615.96,2254.5 ; v1@1800.32,3035 1800,3035.32 v1(1800,3035) v1@1800.32,3035 ; U1.130 U1.130@2615.96,2254.5 ; U1.130 U1.130@2615.96,2254.5
  Top Layer w78.74: 3440,2588.75 3440,2370.75 3480.75,2330 3735,2330 ; 3870,1019.95 3870,1132.17 3945.63,1207.8 DC1.CON 4089.39,1207.8
  Bottom Layer w10: v1(2250,2950) 2327.95,2872.05 v1(2327.95,2757.06)
  other v1: 3485,874.56 3537.5,874.56 3590,874.56 3485,924.56 3537.5,924.56 3590,924.56 3695,1100 3695,1155 4160,1165 3695,1207.8 4160,1217.5 4210,1217.5 1373.16,1245 1418.36,1244.59 1463.55,1244.59 1508.74,1244.59 4160,1270 4210,1270 2565,1280 2617.5,1280 2670,1280 3231.54,1293.73 3284.04,1293.73 3336.54,1293.73 1373.16,1301.54 1418.36,1301.54 1463.55,1301.54 1508.74,1301.54 2565,1330 2617.5,1330 2670,1330 3231.54,1343.73 3284.04,1343.73 3336.54,1343.73 1865,1345 1668.42,1360 1670.45,1405 1720.86,1405 4135,1470 4185,1470 3275,1499.69 3335,1499.69 3395,1499.69 4135,1522.5 4185,1522.5 4135,1575 4185,1575 1487.6,1585 1689.63,1586.38 1521.39,1614.24 1555,1646.33 2910,1659.65 2956.4,1660 1586.53,1675 1760,1675 2716.01,1707.26 2771.22,1707.26 3715,1723 2716.01,1766.53 2771.22,1766.53 840,1770.68 3715,1775 3225,1787.92 3280,1787.92 3336.54,1787.92 1815,1798.99 840,1830 840,1889.32 3655,1896.93 2884.15,1925 3653.81,1943.46 840,1948.64 2920,1955 1970,1960 2022.5,1960 2305,1960 2357.5,1960 2410,1960 2958.66,1990 3653.52,1990 4075,1990 4125,1990 1970,2010 2022.5,2010 2075,2010 2305,2010 4075,2042.5 4125,2042.5 4585,2065 4635,2065 4075,2095 4125,2095 4585,2117.5 4635,2117.5 3886.03,2160 3936.03,2160 4585,2170 4635,2170 1970,2172.01 2022.5,2172.01 2075,2172.01 2305,2172.01 2357.5,2172.01 2410,2172.01 3886.03,2212.5 3936.03,2212.5 1970,2222.01 2022.5,2222.01 2075,2222.01 2305,2222.01 2357.5,2222.01 3886.03,2265 3936.03,2265 3118.78,2372.01 1970,2385 2022.5,2385 2305,2385 2357.5,2385 3118.78,2418.5 2305,2435 2357.5,2435 3691.22,2446.19 3118.78,2465 3725,2471.4 3273.79,2480 3417.02,2485 3465,2485 3520,2485 3273.79,2530 840,2538.07 840,2597.39 1660,2641 1729.01,2641 840,2656.71 2702.84,2660.8 2746.22,2660.8 2789.61,2660.8 3535,2680 3585,2680 2835,2700 2702.84,2701.63 2746.22,2701.63 2789.61,2701.63 3741.11,2702.65 840,2716.03 3836.63,2745 3970,2745 3902.67,2745.79 4422.66,2767.51 4422.66,2820 4420,2870 3830,2873.5 3853.66,2917 4418.58,2920 3795,2926.14 2903.9,3035 2956.4,3035 3008.9,3035 3768.96,3039.21 3902.33,3039.21 3835,3040 2903.9,3085 2956.4,3085 3008.9,3085 1695,3169.29 1745,3169.29 1050,3206.4 1102.5,3206.4 1155,3206.4 4580.46,3210 4630.46,3210 1695,3221.79 1745,3221.79 1050,3256.4 1102.5,3256.4 1155,3256.4 4580.46,3262.5 4630.46,3262.5 1695,3274.29 1745,3274.29 4580.46,3315 4630.46,3315 1000,3465 1052.5,3465 1105,3465 2385,3478.19 2435,3478.19 1000,3515 1052.5,3515 1105,3515 2385,3530.69 2435,3530.69 2385,3583.19 2435,3583.19 2680,3590 2732.63,3590 2785.25,3590 2837.88,3590 3335,3590 3387.63,3590 3440.25,3590 3492.88,3590 3895.26,3590 3947.89,3590 4000.51,3590 4053.14,3590 2680,3630 2732.63,3630 2785.25,3630 2837.88,3630 3335,3630 3387.63,3630 3440.25,3630 3492.88,3630 3895.26,3630 3947.89,3630 4000.51,3630 4053.14,3630
JNTRST: JTAG1.3 R1.1 U1.134 | length 2171.9
  Top Layer w10: U1.134 2778.6,2332.64 2958.66,2512.7 v1(2958.66,2545) ; v1(3800,2565) 3800,2490 3890,2400 3942.41,2400 R1.1 4054.99,2350.01 4170,2235 4251.58,2235 4301.58,2185 JTAG1.3
  Bottom Layer w10: v1(2958.66,2545) 3153.66,2740 3625,2740 v1(3800,2565) v1@3789.24,2565
JTCK: JTAG1.9 R5.2 U1.109 | length 2420.1
  Top Layer w10: U1.109 2740,1840.51 2765.51,1815 v1(2775,1815) ; R5.2 4065,2650 4185,2530 4261.58,2530 4306.58,2485 JTAG1.9
  Bottom Layer w10: v1(2775,1815) 2960,1815 3220,2075 3456.1,2075 3916.1,2535 4265,2535 JTAG1.9
JTDI: JTAG1.5 R2.1 U1.110 | length 2464.7
  Top Layer w10: U1.110 2744.36,1860.2 2756.96,1847.59 v1(2805,1847.59) ; v1@2927.05,1847.59 v1(2925,1847.59) 2925,1755.51 2985.51,1695 v1(2990,1695) ; R2.1 4060,2450 4175,2335 4247.95,2335 4297.95,2285 JTAG1.5
  Bottom Layer w10: v1(2805,1847.59) 2865,1847.59 ; 2867.6,1847.59 v1(2925,1847.59) ; v1(2990,1695) 2999.49,1685.51 3565.51,1685.51 4110,2230 4250,2230 4305,2285 JTAG1.5
JTDO: JTAG1.13 R4.1 U1.133 | length 2232.6
  Top Layer w10: U1.133 2790.89,2312.95 3183.97,2706.03 3183.97,2913.97 3265.32,2995.32 3847.09,2995.32 R4.1 4107.41,2735 4255,2735 4305,2685 JTAG1.13
JTMS: JTAG1.7 R3.1 U1.105 | length 2773.5
  Top Layer w10: U1.105 2485.43,1635 2615.43,1505 v1(2645,1505) ; R3.1 4065,2550 4180,2435 4246.53,2435 4296.53,2385 JTAG1.7
  Bottom Layer w10: v1(2645,1505) 2708.05,1505 3233.05,2030 3880,2030 4180,2330 4260,2330 JTAG1.7
KEY1: S2.3 U1.41 | length 3375.9
  Top Layer w10: U1.41 1644,2450.75 1441.16,2653.58 1441.16,3089.52 1200.5,3330.18 1200.5,3710.5 1340,3850 2252.95,3850 2655,3447.95 S2.3
KEY2: S3.3 U1.42 | length 3991.1
  Top Layer w10: U1.42 1638.94,2431.06 1424.16,2645.84 1424.16,3078.68 1180,3322.84 1180,3725 1324.69,3869.69 2261.11,3869.69 2748.36,3382.43 3212.57,3382.43 S3.3
KEY3: S4.3 U1.43 | length 4663.4
  Top Layer w10: U1.43 1633.62,2411.38 1407.16,2637.84 1407.16,3067.84 1163,3312 1163,3732.04 1320.33,3889.37 2269.26,3889.37 2759.2,3399.43 3800.57,3399.43 S4.3
LIMIT_SW1: P1.5 U1.80 | length 926.8
  Top Layer w10: P1.5 1750,1005 1700,1055 1700,1337.34 1993.31,1630.64 U1.80
LIMIT_SW2: P1.6 U1.81 | length 793.6
  Top Layer w10: P1.6 1750,1353.83 2012.99,1616.83 U1.81
LIMIT_SW3: P1.7 U1.82 | length 901.7
  Top Layer w10: P1.7 1850,996.65 1800,1046.65 1800,1375 2032.68,1607.68 U1.82
LIMIT_SW4: P1.8 U1.87 | length 801.1
  Top Layer w10: P1.8 1850,1244.25 2131.1,1525.35 U1.87
LIMIT_SW5: P1.9 U1.88 | length 909.2
  Top Layer w10: P1.9 1950,993.47 1900,1043.47 1900,1270.21 2150.79,1521 U1.88
LIMIT_SW6: P1.10 U1.89 | length 776
  Top Layer w10: P1.10 1950,1296.17 2170.47,1516.64 U1.89
LIMIT_SW7: P1.11 U1.90 | length 884.1
  Top Layer w10: P1.11 2050,995 2000,1045 2000,1322.12 2190.16,1512.28 U1.90
LIMIT_SW8: P1.12 U1.91 | length 750.9
  Top Layer w10: P1.12 2050,1348.08 2207.16,1505.24 2209.84,1507.93 U1.91
NetD1_2: D1.2 IC1.2 L1.1 | length 569.8
  Top Layer w10: IC1.2 IC1.2@3373.07,2016.93
  Top Layer w30: D1.2@3100,1969.02 3224.02,1845 L1.1 3373.07,1896.93 IC1.2
NetDC1_VCC: DC1.VCC S1.1 S1.4 | length 975.9
  Bottom Layer w59.06: DC1.VCC 3913.78,1350 4475,1350 4560,1435 S1.4 S1.1
NetLED1_1: LED1.1 R6.1 | length 100.5
  Top Layer w10: R6.1 3724.99,2013.73 LED1.1
NetLED2_1: LED2.1 R7.1 | length 117.6
  Top Layer w10: R7.1 LED2.1
NRST: C11.2 JTAG1.15 LCD1.23 R14.1 Reset1.1 U1.25 | length 6349.6
  Top Layer w10: v1(995.95,3320) 1000,3315.95 1000,2625 LCD1.23 ; v1(1225,3415) 1292.6,3347.4 R14.1 1365,3412.4 C11.2 1518.43,3628.43 1518.43,3641.57 ; U1.25 2072.05,2825 2074.73,2827.68 2074.73,2828.77 2100,2854.04 2100,2926.42 2046.42,2980 1965,2980 1870,3075 1870,3250 1685,3435 1685,3545 1518.43,3711.57 1518.43,3641.57 ; v1(3135,3105.35) 3035.35,3205 2594.99,3205 2330,3470 1965,3470 1719.06,3715.94 Reset1.1 1518.43,3641.57
  Bottom Layer w10: v1(995.95,3320) 1090.95,3415 v1(1225,3415) ; v1(3135,3105.35) 3265.35,2975 4040,2975 4180,2835 4265,2835 JTAG1.15
OSC1_IN: C9.2 R8.2 U1.23 Y2.XTAL_2 | length 1096.1
  Top Layer w10: U1.23 2111.42,2811.42 2176.5,2876.5 2410.54,2876.5 2439.04,2905 2602.4,2905 R8.2 C9.2 2720,2977.61 Y2.XTAL_2
OSC1_OUT: C10.2 R8.1 U1.24 Y2.XTAL_1 | length 953.9
  Top Layer w10: U1.24 2091.73,2821.73 2165,2895 2405,2895 2460,2950 C10.2 R8.1 2527.87,2994.72 Y2.XTAL_1
OSC32_IN: C4.2 U1.8 Y1.3 | length 828.5
  Top Layer w10: U1.8 2406.69,2728.69 2445,2767 v1(2495,2767)
  Bottom Layer w10: v1(2495,2767) 2573,2845 2727.32,2845 2750,2822.32 ; C4.2@2758.59,3035.99 C4.2 2762.6,2993.94 2750,2981.34 2750,2822.32 ; Y1.3@2800,2772.32 2750,2822.32
OSC32_OUT: C5.2 U1.9 Y1.1 | length 568.3
  Top Layer w10: U1.9 2387.01,2744.59 2452.42,2810 v1(2495,2810)
  Bottom Layer w10: v1(2495,2810) 2637.4,2952.4 C5.2
RH_DIR: P1.4 U1.45 | length 1779
  Top Layer w10: v1(1520,2465) 1520,2444.98 1592.97,2372.01 U1.45 ; v1(1638.94,1645) 1638.94,1106.69 1633.62,1101.38 P1.4
  Bottom Layer w10: v1(1520,2465) 1520,2238.42 1663.44,2094.99 1663.44,1673.44 1635,1645 v1(1638.94,1645)
RH_SPEED: P1.3 U1.44 | length 1769.9
  Top Layer w10: v1(1580,2425) 1613.31,2391.69 U1.44 ; v1(1603.35,1586.38) 1603.35,1031.65 P1.3
  Bottom Layer w10: v1(1580,2425) 1580,2215 1680.44,2114.56 1680.44,1631.78 1635.04,1586.38 v1(1603.35,1586.38)
RK_SW: ROCKER1.5 U1.15 | length 2628.2
  Top Layer w10: U1.15 2268.9,2656.38 2462.52,2850 3087.15,2850 3340.89,3103.75 4431.25,3103.75 ROCKER1.5
RK_Vx: ROCKER1.3 U1.18 | length 3123.6
  Top Layer w10: U1.18 2209.84,2752.36 2257.48,2800 2388.48,2800 2456.48,2868 3081.1,2868 3333.85,3120.75 4499.25,3120.75 4645,2975 4645,2926.14 4614.15,2895.29 4571.21,2895.29 4535,2859.08 4535,2800 ROCKER1.3
RK_Vy: ROCKER1.4 U1.19 | length 3019.6
  Top Layer w10: U1.19 2190.16,2756.72 2250.44,2817 2342,2817 2384.5,2859.5 2418,2859.5 2443.5,2885 3074.06,2885 3326.81,3137.75 4510.09,3137.75 4662,2985.84 4662,2917 ROCKER1.4
SCREW_DIR: P2.5 U1.28 | length 5561.9
  Top Layer w10: v1(2000,2850) 2000,2840 2012.99,2827.01 U1.28
  Bottom Layer w10: v1(2000,2850) 1998.49,2851.51 1949.85,2851.51 1948.34,2850 1635,2850 1353.4,3131.6 1127.55,3131.6 1121.59,3131.6 1118.51,3131.6 923.43,2936.52 923.43,1258.43 1297.86,884 2979,884 P2.5
SCREW_ENABLE: P2.7 U1.26 | length 5908.6
  Top Layer w10: U1.26 2052.36,2840 2065,2852.64 v1(2065,2910)
  Bottom Layer w10: v1(2065,2910) 1624.04,2910 1368.45,3165.6 1104.43,3165.6 888.75,2949.92 888.75,1233.71 1272.47,850 3045,850 P2.7
SCREW_PWM: P2.3 U1.35 | length 5106.5
  Top Layer w10: v1(1850,2770) 1850,2755 1875.2,2729.8 U1.35
  Bottom Layer w10: v1(1850,2770) 1825.5,2794.5 1635.5,2794.5 1332.4,3097.6 1132.6,3097.6 962.32,2927.32 962.32,1297.32 1341.64,918 2913,918 P2.3
SD_CLK: SD1.5 U1.113 | length 1534.5
  Top Layer w10: U1.113 v1(2701.85,1919.25)
  Bottom Layer w10: v1(2701.85,1919.25) 2704.25,1919.25 2720,1935 2720,2025 2780,2085 2883.18,2085 3030,2231.82 3030,2555.92 3159.08,2685 3441.42,2685 3494.72,2631.69 SD1.5
SD_CMD: R11.2 SD1.3 U1.116 | length 1630.6
  Top Layer w10: U1.116 2783.31,1978.31 2815,2010 v1(2867.6,2010) ; v1(3385,2640) 3365,2660 3365,2725 3402.7,2762.7 3415,2762.7 R11.2
  Bottom Layer w10: v1(2867.6,2010) 3005,2147.4 3005,2182.77 3047,2224.77 3047,2548.88 3158.12,2660 3365,2660 v1(3385,2640) 3400,2625 3400,2566.5 SD1.3
SD_DATA0: R12.2 SD1.7 U1.98 | length 2795
  Top Layer w10: U1.98 2347.64,1647.36 v1(2357.5,1637.5) ; v1(2695,2105) 2728,2138 2758.96,2138 2832.96,2212 3041.39,2212 3064.39,2235 v1(3110,2235) ; R12.2 3586.25,2773.75 3670,2690 v1(3670,2625)
  Bottom Layer w10: v1(2357.5,1637.5) 2357.5,1632.5 2380,1610 2540,1610 2620,1690 2620,2070.96 2654.04,2105 v1(2695,2105) ; v1(3110,2235) 3127.27,2217.73 3574.79,2217.73 3780,2422.94 3780,2550.2 3705.2,2625 v1(3670,2625) 3625.08,2625 3598.87,2598.79 3598.87,2575.91 SD1.7
SD_DATA1: R13.2 SD1.8 U1.99 | length 2348.2
  Top Layer w10: U1.99 v1(2367.32,1860) ; v1(2695,2155) 2751.92,2155 2825.92,2229 3034.35,2229 3085.35,2280 v1(3115,2280) ; v1(3675,2400) 3701.21,2400 3768.58,2467.37 3768.58,2743.58 3750,2762.16 3750,2807.01 3705.67,2851.34 3691.14,2851.34 R13.2
  Bottom Layer w10: v1(2367.32,1860) 2662.32,2155 v1(2695,2155) ; v1(3115,2280) 3115,2281 3420.65,2281 3624.65,2485 ; SD1.8 3624.65,2485 ; v1(3675,2400) 3624.65,2450.35 3624.65,2485
SD_DATA2: R9.2 SD1.1 U1.111 | length 1612.8
  Top Layer w10: U1.111 2682.53,1879.88 2684.66,1877.75 2775.06,1877.75 v1(2777.19,1879.88) ; v1(3098.66,2053.66) 3098.66,2163.66 3145,2210 v1(3145,2312.95) ; v1(3210,2583.92) 3210,2745.2 3260,2795.2 R9.2
  Bottom Layer w10: v1(2777.19,1879.88) 2924.88,1879.88 v1(3098.66,2053.66) ; v1(3145,2312.95) 3212.95,2312.95 3321.5,2421.5 SD1.1 3321.5,2560.43 3298.01,2583.92 v1(3210,2583.92)
SD_DATA3: R10.2 SD1.2 U1.112 | length 1582.3
  Top Layer w10: U1.112 2686.89,1899.57 2691.71,1894.75 2730.07,1894.75 v1(2745,1909.69) v1@2750,1909.69 ; v1(3330,2630) 3330,2765 3398.75,2833.75 R10.2
  Bottom Layer w10: v1(2745,1909.69) 2795.31,1960 2860,1960 3030,2130 3030,2183.73 3064,2217.73 3064,2541.84 3152.16,2630 v1(3330,2630) 3347.28,2630 3364.8,2612.47 SD1.2
T_INT: LCD1.26 U1.22 | length 1613.4
  Top Layer w10: U1.22 2131.1,2804.14 2186.46,2859.5 2270.5,2859.5 v1(2280,2850)
  Bottom Layer w10: LCD1.26 1345,2760 1572.88,2760 1621.38,2711.5 2181.5,2711.5 2280,2810 v1(2280,2850)
T_MISO: LCD1.25 U1.20 | length 1816.9
  Top Layer w10: U1.20 2170.47,2780.47 v1(2185,2795)
  Bottom Layer w10: LCD1.25 1105,2661.27 1146.53,2702.8 1146.53,2996.21 1193.31,3043 1313.92,3043 1628.42,2728.5 1867.19,2728.5 1923.69,2785 2175,2785 v1(2185,2795) 2185.32,2795 v1@2190.16,2799.84
T_MOSI: LCD1.27 U1.21 | length 1868
  Top Layer w10: U1.21 2150.79,2725 2151,2725.21 2151,2800 2186,2835 v1(2200,2835)
  Bottom Layer w10: LCD1.27 1044.64,2780.36 1044.64,2918.37 1186.27,3060 1320.96,3060 1635.46,2745.5 1860.15,2745.5 1917.16,2802.51 2153.51,2802.51 2186,2835 v1(2200,2835)
T_SCK: LCD1.29 U1.47 | length 925.5
  Top Layer w10: LCD1.29 1157.49,2767.51 1224.56,2767.51 1379,2613.06 1379,2537.9 1584.26,2332.64 U1.47
TP_CS: LCD1.31 U1.48 | length 1172.7
  Top Layer w10: LCD1.31 1089.16,2920 1017,2847.84 1017,2735.82 1082.82,2670 1222.86,2670 1579.91,2312.95 U1.48
UART3_RX: U1.70 UART1.3 | length 3148.5
  Top Layer w10: UART1.3 835,3155 835,3055 895,2995 895,1430 1045,1280 v1(1220,1280) ; v1(1633.62,1810.39) 1703.11,1879.88 U1.70
  Bottom Layer w10: v1(1220,1280) 1285,1280 1387,1382 1387,1563.77 v1(1633.62,1810.39)
UART3_TX: U1.69 UART1.4 | length 2961.2
  Top Layer w10: UART1.4 915,3120 915,3045 915,1440 1035,1320 v1(1215,1320) ; v1(1623.15,1855.49) 1632.9,1855.49 1676.97,1899.57 U1.69
  Bottom Layer w10: v1(1215,1320) 1270,1320 1370,1420 1370,1602.34 v1(1623.15,1855.49)
VBAT: BT1.VBAT U1.6 | length 730.7
  Top Layer w10: v1(2445,2730) 2445,2601.42 U1.6
  Top Layer w15: BT1.VBAT v1(2190,3085)
  Bottom Layer w15: v1(2190,3085) 2445,2830 v1(2445,2730)
VREF+: C7.1 C8.1 L2.2 U1.32 U1.33 | length 1730.5
  Top Layer w10: C7.1 1497.6,3414.81 C8.1 1635,3277.41 1635,3150 L2.2 ; U1.33 1914.57,2725 1874.5,2765.07 1874.5,2780.15 1575,3079.65 L2.2 ; U1.32 1934.25,2730.75 L2.2
WHEEL_DIR: P2.6 U1.29 | length 5543.9
  Top Layer w10: v1(1960,2827.01) 1960,2800 1993.31,2766.69 U1.29
  Bottom Layer w10: v1(1960,2827.01) 1632.99,2827.01 1345.4,3114.6 1134.59,3114.6 1125.55,3114.6 941.11,2930.15 941.11,1276.11 1316.22,901 2964.37,901 3031.05,967.68 3031.05,1036.05 P2.6 P2.6@3080,1060.49
WHEEL_ENABLE: P2.2 U1.27 | length 6179.6
  Top Layer w10: U1.27 2032.68,2850 2037,2854.32 v1(2037,2880)
  Bottom Layer w10: v1(2037,2880) 1629.04,2880 1360.45,3148.6 1111.47,3148.6 905.75,2942.88 905.75,1242.11 1280.86,867 3037.96,867 3130,959.04 3130,1115.74 3090.74,1155 2950,1155 P2.2
WHEEL_PWM: P2.4 U1.36 | length 5036.9
  Top Layer w10: v1(1805,2770) 1810.51,2770 1855.51,2725 U1.36
  Bottom Layer w10: v1(1805,2770) 1635,2770 1326.32,3078.68 1138.68,3078.68 980,2920 980,1315 1360,935 2753.97,935 2852.73,1033.75 2928.75,1033.75 P2.4
WHEEL_SPEED: P2.8 U1.136 | length 1678.4
  Top Layer w10: U1.136 2745.31,2372.01 v1(2757.32,2360) ; v1(2665,1601.37) 2665,1600 P2.8
  Bottom Layer w10: v1(2665,1601.37) 2664.42,1601.37 2659.49,1606.3 2667,1613.82 2667,2027 2757.32,2117.32 v1(2757.32,2360)
pads on no net: BT1.0 JTAG1.11 JTAG1.17 JTAG1.19 LCD1.28 LCD1.30 LCD1.32 S1.3 S1.6 S2.2 S2.4 S3.2 S3.4 S4.2 S4.4 SD1.0 SD1.9 U1.1 U1.2 U1.3 U1.4 U1.5 U1.7 U1.10 U1.11 U1.12 U1.13 U1.14 U1.34 U1.37 U1.40 U1.49 U1.50 U1.53 U1.54 U1.55 U1.57 U1.73 U1.74 U1.75 U1.76 U1.104 U1.106 U1.117 U1.122 U1.123 U1.124 U1.125 U1.126 U1.128 U1.129 U1.132 U1.135 U1.137 U1.139 U1.140 U1.141 U1.142 Y1.2 Y1.4

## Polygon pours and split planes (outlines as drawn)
GND on Top Layer "Bottom Layer-No Net" (solid, remove dead copper, pour order 20): 1193.31,3915 1193.31,3550 825,3550 810,3535 810,1185 1190,805 4315,805 4315,1195 4700,1195 4700,3545 4330,3545 4330,3920
GND on Bottom Layer "GND_L02_P017" (solid, remove dead copper, pour order 17): 1193.31,3915 1193.31,3550 825,3550 810,3535 810,1185 1190,805 4315,805 4315,1195 4700,1195 4700,3545 4330,3545 4330,3920

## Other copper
Top Layer:
  pour cut-out: 839.68,1173.35 839.68,1000 1349.68,1000 1349.68,1173.35
  text "MainBoard_1.1" at 854.61,1110 h40
  text "19.4.18   SEU_SZK" at 854.61,1033.67 h30

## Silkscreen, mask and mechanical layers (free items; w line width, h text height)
Top Solder:
  rectangle: 845,1010 1340,1165
Mechanical 1:
  the board outline again, w10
